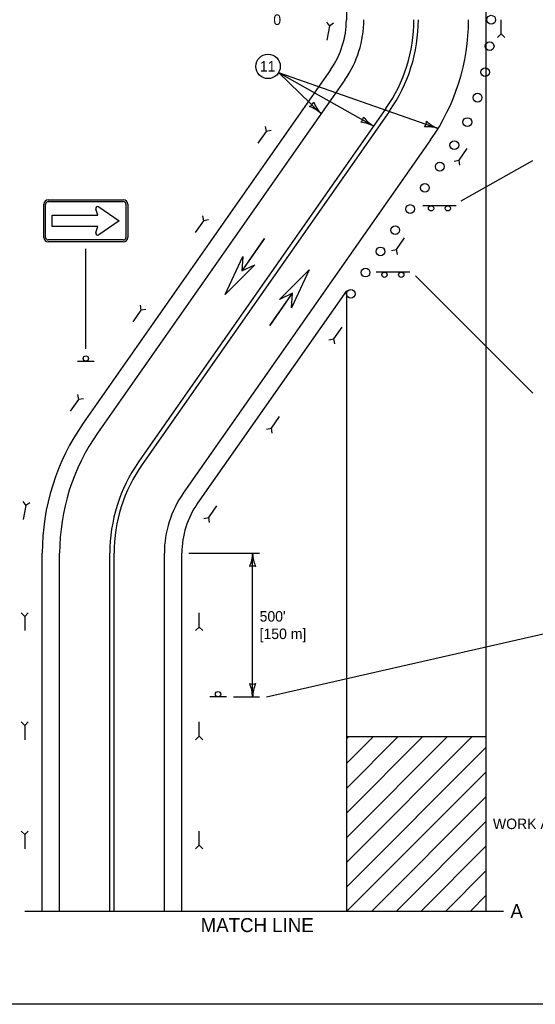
# Model space of a CAD drawing. Extents: x 49991.4 to 50021, y 49987.6 to 50011.4.
# Drawn here: x 50008.68 to 50011.63, y 49987.8 to 49993.44 of the extents above; entities that cross this region are included whole.
import ezdxf

# ---------------------------------------------------------------- set-up
doc = ezdxf.new("R2010")
doc.units = 0
for name, color, linetype in [('Level 1', 7, 'Continuous'), ('Level 2', 7, 'Continuous'), ('Level 3', 7, 'Continuous'), ('Level 6', 7, 'Continuous')]:
    doc.layers.add(name, color=color, linetype=linetype)

msp = doc.modelspace()

# ---------------------------------------------------------------- linework, layer by layer
at = {"layer": 'Level 1'}
for p, q in [((50010.5474, 49998.459), (50010.5474, 49993.4398)), ((50011.3474, 49998.459), (50011.3474, 49989.3327)), ((50011.4344, 49993.3584), (50011.4343, 49993.4398)), ((50010.4333, 49993.4262), (50010.45, 49993.4026)), ((50010.45, 49993.4026), (50010.4364, 49993.3223)), ((50010.4736, 49993.4194), (50010.45, 49993.4026)), ((50011.4142, 49993.3379), (50011.4344, 49993.3584)), ((50011.455, 49993.3379), (50011.4344, 49993.3584)), ((50010.4569, 49993.1529), (50009.0394, 49991.1285)), ((50010.5389, 49993.0955), (50009.1214, 49991.0711)), ((50010.7745, 49992.9305), (50009.357, 49990.9061)), ((50010.7949, 49992.9162), (50009.3774, 49990.8918)), ((50010.0823, 49992.8276), (50010.0871, 49992.7992)), ((50010.0871, 49992.7992), (50010.0405, 49992.7325)), ((50010.1157, 49992.8042), (50010.0871, 49992.7992)), ((50011.0304, 49992.7513), (50009.6129, 49990.7269)), ((50011.1933, 49992.635), (50011.2399, 49992.7017)), ((50011.1647, 49992.63), (50011.1933, 49992.635)), ((50011.1981, 49992.6066), (50011.1933, 49992.635)), ((50008.8144, 49992.1927), (50008.8144, 49992.3827)), ((50008.8244, 49992.1927), (50008.8244, 49992.3827)), ((50008.8394, 49992.4077), (50009.2694, 49992.4077)), ((50008.8394, 49992.3977), (50009.2694, 49992.3977)), ((50009.1299, 49992.3679), (50009.2465, 49992.2877)), ((50009.2844, 49992.3827), (50009.2844, 49992.1927)), ((50009.2944, 49992.3827), (50009.2944, 49992.1927)), ((50011.0808, 49992.3743), (50010.9848, 49992.3743)), ((50011.1768, 49992.3743), (50011.0808, 49992.3743)), ((50008.8623, 49992.2557), (50008.8623, 49992.3197)), ((50008.8623, 49992.3197), (50009.1226, 49992.3197)), ((50009.1226, 49992.3197), (50009.1114, 49992.3541)), ((50009.7238, 49992.3157), (50009.7286, 49992.2873)), ((50009.1047, 49992.2557), (50008.8623, 49992.2557)), ((50009.1226, 49992.2557), (50009.1047, 49992.2557)), ((50009.1114, 49992.2214), (50009.1226, 49992.2557)), ((50009.2465, 49992.2877), (50009.1299, 49992.2075)), ((50009.7286, 49992.2873), (50009.682, 49992.2206)), ((50009.7572, 49992.2923), (50009.7286, 49992.2873)), ((50010.8348, 49992.1231), (50010.8814, 49992.1898)), ((50009.2694, 49992.1777), (50008.8394, 49992.1777)), ((50009.2694, 49992.1677), (50008.8394, 49992.1677)), ((50010.0774, 49992.186), (50009.9478, 49992.0009)), ((50010.0776, 49992.1859), (50009.948, 49992.0008)), ((50010.8062, 49992.1181), (50010.8348, 49992.1231)), ((50010.8396, 49992.0947), (50010.8348, 49992.1231)), ((50010.8142, 49991.9935), (50010.7182, 49991.9935)), ((50010.9102, 49991.9935), (50010.8142, 49991.9935)), ((50010.5474, 49991.887), (50009.6949, 49990.6695)), ((50010.1098, 49991.6872), (50010.2394, 49991.8723)), ((50010.11, 49991.6871), (50010.2396, 49991.8722)), ((50010.5474, 49991.887), (50010.5474, 49989.3327)), ((50009.3653, 49991.8037), (50009.3701, 49991.7753)), ((50009.3701, 49991.7753), (50009.3235, 49991.7086)), ((50009.3987, 49991.7803), (50009.3701, 49991.7753)), ((50010.4763, 49991.6111), (50010.5229, 49991.6778)), ((50010.4477, 49991.6061), (50010.4763, 49991.6111)), ((50010.4811, 49991.5827), (50010.4763, 49991.6111)), ((50009.0064, 49991.4834), (50009.1024, 49991.4834)), ((50009.0069, 49991.2917), (50009.0117, 49991.2633)), ((50009.0117, 49991.2633), (50008.9651, 49991.1966)), ((50009.0403, 49991.2683), (50009.0117, 49991.2633)), ((50010.1178, 49991.0991), (50010.1644, 49991.1658)), ((50010.0892, 49991.0941), (50010.1178, 49991.0991)), ((50010.1226, 49991.0707), (50010.1178, 49991.0991)), ((50008.6934, 49990.6796), (50008.7099, 49990.6559)), ((50008.7336, 49990.6726), (50008.7099, 49990.6559)), ((50008.7099, 49990.6559), (50008.6959, 49990.5757)), ((50009.7593, 49990.5871), (50009.8059, 49990.6538)), ((50009.7307, 49990.5821), (50009.7593, 49990.5871)), ((50009.7641, 49990.5587), (50009.7593, 49990.5871)), ((50008.8044, 49988.3327), (50008.8044, 49990.3826)), ((50008.9044, 49988.3327), (50008.9044, 49990.3826)), ((50009.1919, 49988.3327), (50009.1919, 49990.3826)), ((50009.2169, 49988.3327), (50009.2169, 49990.3826)), ((50009.5044, 49988.3327), (50009.5044, 49990.3826)), ((50009.6044, 49988.3327), (50009.6044, 49990.3826)), ((50008.6843, 49990.0416), (50008.7046, 49990.0211)), ((50008.7251, 49990.0416), (50008.7046, 49990.0211)), ((50008.7046, 49990.0211), (50008.7046, 49989.9397)), ((50009.7044, 49989.9603), (50009.7044, 49990.0417)), ((50009.6839, 49989.9398), (50009.7044, 49989.9603)), ((50009.7247, 49989.9398), (50009.7044, 49989.9603)), ((50009.8604, 49989.5602), (50009.7644, 49989.5602)), ((50008.6843, 49989.4166), (50008.7046, 49989.3961)), ((50008.7251, 49989.4166), (50008.7046, 49989.3961)), ((50008.7046, 49989.3961), (50008.7046, 49989.3147)), ((50009.7044, 49989.3353), (50009.7044, 49989.4167)), ((50009.6839, 49989.3148), (50009.7044, 49989.3353)), ((50009.7247, 49989.3148), (50009.7044, 49989.3353)), ((50010.5474, 49989.3327), (50011.3474, 49989.3327)), ((50010.5474, 49989.3327), (50010.5474, 49988.3327)), ((50010.5474, 49988.6119), (50011.2682, 49989.3327)), ((50010.5474, 49988.7533), (50011.1268, 49989.3327)), ((50010.5474, 49988.8947), (50010.9854, 49989.3327)), ((50010.5474, 49989.0361), (50010.844, 49989.3327)), ((50010.5474, 49989.1775), (50010.7026, 49989.3327)), ((50010.5474, 49989.319), (50010.5611, 49989.3327)), ((50011.3474, 49989.3327), (50011.3474, 49988.3327)), ((50010.5474, 49988.4705), (50011.3474, 49989.2705)), ((50010.551, 49988.3327), (50011.3474, 49989.1291)), ((50010.6925, 49988.3327), (50011.3474, 49988.9876)), ((50010.8339, 49988.3327), (50011.3474, 49988.8462)), ((50008.6843, 49988.7916), (50008.7046, 49988.7711)), ((50008.7251, 49988.7916), (50008.7046, 49988.7711)), ((50008.7046, 49988.7711), (50008.7046, 49988.6897)), ((50009.7044, 49988.7103), (50009.7044, 49988.7917)), ((50009.6839, 49988.6898), (50009.7044, 49988.7103)), ((50009.7247, 49988.6898), (50009.7044, 49988.7103)), ((50010.9753, 49988.3327), (50011.3474, 49988.7048)), ((50011.1167, 49988.3327), (50011.3474, 49988.5634)), ((50011.2581, 49988.3327), (50011.3474, 49988.422))]:
    msp.add_line(p, q, dxfattribs=at)
for points in [[(49999.3835, 49998.9992), (50016.7501, 49998.9992), (50016.7501, 49987.7988), (49999.3835, 49987.7988)], [(50010.0236, 49992.0361), (50009.8538, 49991.8663), (50009.9551, 49992.084), (50009.9481, 49992.0009)], [(50010.1638, 49991.837), (50010.3336, 49992.0068), (50010.2323, 49991.7891), (50010.2393, 49991.8722)]]:
    msp.add_lwpolyline(points, close=True, dxfattribs=at)
for centre, radius in [((50011.3779, 49993.4398), 0.025), ((50011.3684, 49993.2884), 0.025), ((50011.3425, 49993.1388), 0.025), ((50011.2996, 49992.9931), 0.025), ((50011.2405, 49992.8533), 0.025), ((50011.166, 49992.7213), 0.025), ((50011.0825, 49992.5978), 0.025), ((50010.9976, 49992.4767), 0.025), ((50010.9126, 49992.3551), 0.025), ((50011.0328, 49992.3591), 0.0152), ((50011.1288, 49992.3591), 0.0152), ((50010.8277, 49992.2337), 0.025), ((50010.7427, 49992.1122), 0.025), ((50010.6577, 49991.9907), 0.025), ((50010.7662, 49991.9783), 0.0152), ((50010.8622, 49991.9783), 0.0152), ((50010.5728, 49991.8692), 0.025), ((50009.0544, 49991.4986), 0.0152), ((50009.8124, 49989.5754), 0.0152)]:
    msp.add_circle(centre, radius, dxfattribs=at)
for centre, radius, start, end in [((50010.0474, 49993.4398), 0.5, 324.9919, 0), ((50010.0474, 49993.4398), 0.6, 324.9919, 0), ((50010.0474, 49993.4398), 0.8875, 324.9919, 0), ((50010.0474, 49993.4398), 0.9125, 324.9919, 0), ((50010.0474, 49993.4398), 1.2, 324.9919, 0), ((50008.8394, 49992.3827), 0.025, 90, 180), ((50008.8394, 49992.3827), 0.015, 90, 180), ((50009.123, 49992.3578), 0.0122, 55.4806, 197.9582), ((50009.2694, 49992.3827), 0.025, 0, 90), ((50009.2694, 49992.3827), 0.015, 0, 90), ((50008.8394, 49992.1927), 0.025, 180, 270), ((50008.8394, 49992.1927), 0.015, 180, 270), ((50009.123, 49992.2175), 0.0122, 162.0418, 304.5194), ((50009.2694, 49992.1927), 0.025, 270, 0), ((50009.2694, 49992.1927), 0.015, 270, 0), ((50010.1044, 49990.3826), 1.3, 144.9919, 180), ((50010.1044, 49990.3826), 1.2, 144.9919, 180), ((50010.1044, 49990.3826), 0.9125, 144.9919, 180), ((50010.1044, 49990.3826), 0.8875, 144.9919, 180), ((50010.1044, 49990.3826), 0.6, 144.9919, 180), ((50010.1044, 49990.3826), 0.5, 144.9919, 180)]:
    msp.add_arc(centre, radius, start, end, dxfattribs=at)
at = {"layer": 'Level 2'}
msp.add_circle((50010.0987, 49993.1724), 0.07, dxfattribs=at)
at = {"layer": 'Level 3'}
for p, q in [((50010.1592, 49993.1373), (50010.4029, 49992.9013)), ((50010.1592, 49993.1373), (50010.7039, 49992.8296)), ((50010.1592, 49993.1373), (50011.0729, 49992.8167)), ((50011.2049, 49992.4028), (50011.6162, 49992.6336)), ((50009.0544, 49991.5538), (50009.0544, 49992.1277)), ((50010.9437, 49991.9715), (50011.6157, 49991.3008)), ((50009.6444, 49990.3826), (50010.0504, 49990.3826)), ((50010.0104, 49989.5602), (50010.0104, 49990.3826)), ((50010.0904, 49989.5602), (50011.8749, 49989.9678)), ((50009.9004, 49989.5602), (50010.0504, 49989.5602))]:
    msp.add_line(p, q, dxfattribs=at)
for centre, radius, start, end in [((50010.3112, 49992.9909), 0.0548, 297.8208, 333.5432), ((50010.2486, 49992.7268), 0.233, 48.5093, 67.7592), ((50010.5647, 49993.0538), 0.2223, 203.138, 223.3215), ((50010.5925, 49992.8931), 0.0548, 312.4386, 348.1609), ((50010.8219, 49993.018), 0.2223, 217.7558, 237.9393), ((50010.5985, 49992.6218), 0.233, 63.1271, 82.3769), ((50010.9521, 49992.8596), 0.0548, 322.5662, 358.2886), ((50011.0058, 49992.5936), 0.233, 73.2547, 92.5046), ((50011.156, 49993.0229), 0.2223, 227.8834, 248.0669), ((50009.7883, 49990.3918), 0.2223, 337.456, 357.6395), ((50010.2431, 49990.3941), 0.233, 182.8273, 202.0772), ((50010.0104, 49990.2544), 0.0548, 72.1388, 107.8612), ((50010.0104, 49989.6884), 0.0548, 252.1388, 287.8612), ((50009.7777, 49989.5487), 0.233, 2.8273, 22.0772), ((50010.2325, 49989.5511), 0.2223, 157.456, 177.6395)]:
    msp.add_arc(centre, radius, start, end, dxfattribs=at)
at = {"layer": 'Level 6'}
msp.add_line((50008.7044, 49988.3327), (50011.4474, 49988.3327), dxfattribs=at)

# ---------------------------------------------------------------- texts
at = {"layer": 'Level 2'}
for s, height, p in [('0', 0.06, (50010.1288, 49993.4098)), ('11', 0.06, (50010.052, 49993.1424)), ("500'", 0.06, (50010.0504, 49989.9914)), ('[150 m]', 0.06, (50010.0504, 49989.8914)), ('WORK AREA', 0.06, (50011.3874, 49988.8027)), ('A', 0.08, (50011.4874, 49988.2927)), ('MATCH LINE', 0.08, (50009.7125, 49988.2127))]:
    msp.add_text(s, height=height, dxfattribs=at).set_placement(p)

doc.saveas('drawing.dxf')
